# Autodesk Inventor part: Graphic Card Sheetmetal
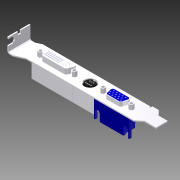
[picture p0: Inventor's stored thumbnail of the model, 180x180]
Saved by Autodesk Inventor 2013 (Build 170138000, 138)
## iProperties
Created: 2005-12
Material: Allgemein
Document SubType Name: Sheet Metal
Mass: 18.5516 g
Surface Area: 105.188 cm^2
Volume: 18.5516 cm^3
Density: 1 g/cm^3
Sheet Metal Rule: 1.0 mm
Author: Autodesk, Inc.
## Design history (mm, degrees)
node "Face1"
node "Flange1"
node "Face2"
sketch "Sketch5"
  geometry: L1 (108, 0)-(0, 0) reference; L2 (108, 18.5)-(108, 0) reference; L3 (108, 18.5)-(90.571, 18.5) reference; L4 (108, 9.25)-(96.897, 9.25); L5 (96, 18.5)-(100, 14.25); L6 (100, 14.25)-(108, 14.25); L7 (93, 0)-(98, 4.25); L8 (98, 4.25)-(108, 4.25)
  constraints: 10 end point, 4 point on line, 2 parallel, 1 midpoint, 1 perpendicular, 1 other
  dimensions: "d32" = 10 distance between parallel lines of L8 L6; "d33" = 12 distance from line of L5.start L2; "d34" = 15 distance from line of L2 L7.start; "d35" = 8 distance of L5.end L6.end; "d36" = 10 distance of L7.end L8.end
cut "Cut2" sketch "Sketch5" dims "d37" = 1 (= Thickness), "d38" = 0
node "Flange2"
sketch "Sketch7" dims "d47" = 5
  geometry: L1 (0, 0)-(0, 19) reference; L2 (10.5, 0)-(0, 0) reference; L3 (1.5, 0)-(6.5, 0); L4 (6.5, 0)-(6.5, 3); L5 (6.5, 3)-(1.5, 3); L6 (1.5, 3)-(1.5, 0); L7 (0, 9.5)-(6.587, 9.5); L8 (0, 10.75)-(2.5, 10.75); L9 (2.5, 10.75)-(2.5, 8.25); L10 (2.5, 8.25)-(0, 8.25); L11 (0, 8.25)-(0, 10.75); 1 further point
  constraints: 18 end point, 4 parallel, 4 perpendicular, 2 horizontal, 2 midpoint, 2 point on line, 1 horizontal alignment, 3 other
  dimensions: "d46" = 2.5 distance of L8.start L8.end; "d166" = 3 distance between parallel lines of L2 L5; "d167" = 4 distance from line of point (4, 3) L1
cut "Cut3" sketch "Sketch7" dims "d48" = 1 (= Thickness), "d49" = 0
sketch "Sketch8"
  geometry: L1 (-18.429, -2.75)-(-18.429, -12.75) reference; L2 (-3.429, -17)-(89.571, -17) reference; L3 (3.571, -2)-(34.071, -2); L4 (34.071, -2)-(34.071, -14); L5 (34.071, -14)-(3.571, -14); L6 (3.571, -14)-(3.571, -2)
  constraints: 8 end point, 2 parallel, 1 horizontal, 1 perpendicular
  dimensions: "d50" = 22 distance between parallel lines of L1 L6; "d51" = 30.5 distance of L3.start L3.end; "d52" = 12 distance of L3.end L4.end; "d53" = 3 distance between parallel lines of L2 L5
extrude "Extrusion1" join sketch "Sketch8" distance "d54" = 18; taper "d55" = 0 deg
sketch "Sketch9"
  geometry: L1 (30.5, 0)-(0, 0) reference; L2 (30.5, -18)-(30.5, 0) reference; L3 (30.5, 0)-(24.5, 0); L4 (24.5, 0)-(24.5, -10); L5 (24.5, -10)-(30.5, -10); L6 (30.5, -10)-(30.5, 0); L7 (0, 0)-(6, 0); L8 (6, 0)-(6, -10); L9 (6, -10)-(0, -10); L10 (0, -10)-(0, 0)
  constraints: 16 end point, 4 parallel, 2 collinear, 2 horizontal, 2 perpendicular
  dimensions: "d56" = 6 distance between parallel lines of L2 L4; "d57" = 10 distance between parallel lines of L5 L1
extrude "Extrusion2" cut sketch "Sketch9" distance "d58" = 10; taper "d59" = 0 deg
sketch "Sketch10"
  geometry: L1 (0, 0)-(0, 8) reference; L2 (30.5, 0)-(30.5, 8) reference; L3 (24.5, 18)-(6, 18) reference; L4 (0, 4)-(30.5, 4); L5 (30.5, 4)-(30.5, 18); L6 (30.5, 18)-(0, 18); L7 (0, 18)-(0, 4)
  constraints: 8 end point, 2 collinear, 2 parallel, 1 horizontal, 1 midpoint, 1 perpendicular
extrude "Extrusion3" cut sketch "Sketch10" distance "d60" = 1; taper "d61" = 0 deg
sketch "Sketch11"
  geometry: L1 (24.5, -10)-(30.5, -10) reference; L2 (24.5, 0)-(30.5, 0) reference; L3 (0, -10)-(6, -10) reference; L4 (6, -10)-(6, 0) reference; L5 (0, 0)-(6, 0) reference; L6 (0, -10)-(0, 0) reference; L7 (27.5, 0)-(27.5, -10); L8 (3, 0)-(3, -10); L9 (25.5, 0)-(29.5, 0); L10 (29.5, 0)-(29.5, -6); L11 (29.5, -6)-(25.5, -6); L12 (25.5, -6)-(25.5, 0); L13 (1, 0)-(5, 0); L14 (5, 0)-(5, -6); L15 (5, -6)-(1, -6); L16 (1, -6)-(1, 0); 2 further points
  constraints: 20 end point, 6 midpoint, 5 parallel, 2 horizontal, 2 horizontal alignment, 2 perpendicular, 2 point on line, 6 other
  dimensions: "d63" = 4 distance between parallel lines of L10 L12; "d64" = 6 distance between parallel lines of L15 L13
extrude "Extrusion4" cut sketch "Sketch11" stored distance "d65" = 0.5; taper "d66" = 0 deg
sketch "Sketch12"
  geometry: L1 (97.571, -17)-(4.571, -17) reference; L2 (90.571, -2)-(60.071, -2) reference; L3 (75.321, -2)-(75.321, -17); L4 (69.321, -5)-(81.321, -5); L5 (83.262, -7.485)-(82.262, -11.485); L6 (80.321, -13)-(70.321, -13); L7 (68.381, -11.485)-(67.381, -7.485); A1 r 2 centre (69.321, -7) between (69.321, -5) and (67.381, -7.485); A2 r 2 centre (81.321, -7) between (83.262, -7.485) and (81.321, -5); A3 r 2 centre (70.321, -11) between (68.381, -11.485) and (70.321, -13); A4 r 2 centre (80.321, -11) between (80.321, -13) and (82.262, -11.485)
  constraints: 10 end point, 8 point on circle, 8 tangent, 4 centre point, 2 equal radius, 2 perpendicular, 1 midpoint, 1 parallel, 1 point on line, 1 other
  dimensions: "d73" = 8 distance between parallel lines of L6 L4; "d74" = 4 distance between parallel lines of L1 L6; "d75" = 2 radius of A1; "d76" = 16 dimension on A2 A1; "d77" = 2 radius of A3; "d78" = 10 distance of L6.start L6.end
extrude "Extrusion5" join sketch "Sketch12" distance "d79" = 3.5; taper "d80" = 0 deg
sketch "Sketch13"
  geometry: L1 (69.321, -5)-(81.321, -5) reference; L2 (80.321, -13)-(70.321, -13) reference; L3 (75.321, -5)-(75.321, -13); L4 (75.321, -9)-(79.071, -9); L5 (70.321, -7)-(80.321, -7); L6 (77.821, -7)-(79.071, -9); L7 (80.321, -7)-(79.071, -9); L8 (70.321, -11)-(80.321, -11); C1 r 0.5 at (75.321, -7); C2 r 0.5 at (77.821, -7); C3 r 0.5 at (80.321, -7); C4 r 0.5 at (72.821, -7); C5 r 0.5 at (70.321, -7); C6 r 0.5 at (79.071, -9); C7 r 0.5 at (76.571, -9); C8 r 0.5 at (74.071, -9); C9 r 0.5 at (71.571, -9); C10 r 0.5 at (69.071, -9); C11 r 0.5 at (80.321, -11); C12 r 0.5 at (77.821, -11); C13 r 0.5 at (75.321, -11); C14 r 0.5 at (70.321, -11); C15 r 0.5 at (72.821, -11); A1 r 2 centre (69.321, -7) between (69.321, -5) and (67.381, -7.485) reference; 1 further point
  constraints: 15 centre point, 12 end point, 9 equal radius, 9 symmetric about line, 7 point on line, 5 coincident, 5 midpoint, 4 horizontal alignment, 1 equal length, 1 parallel, 1 perpendicular, 5 other
  dimensions: "d81" = 2 distance between parallel lines of L5 L1; "d82" = 2.5 distance of L6.start C1.centre (= d83); "d83" = 2.5 distance of L5.end L6.start; "d84" = 2.5 distance of C1.centre C4.centre (= d82); "d85" = 1 diameter of C3; "d86" = 2.5 distance of L4.end C7.centre (= d83); "d87" = 2.5 distance of C7.centre C8.centre (= d86); "d88" = 2.5 distance of C8.centre C9.centre (= d87); "d89" = 2.5 distance of C9.centre C10.centre (= d88)
extrude "Extrusion6" cut sketch "Sketch13" distance "d90" = 8; taper "d91" = 0 deg
split "Split1"
sketch "Sketch15"
  geometry: L1 (97.571, -17)-(4.571, -17) reference; L2 (112.571, -2.75)-(112.571, -12.75) reference; C1 r 5 at (50.571, -8)
  constraints: 1 centre point
  dimensions: "d93" = 9 distance from line of L1 C1.centre; "d94" = 62 distance from line of L2 C1.centre; "d95" = 10 diameter of C1
extrude "Extrusion7" cut sketch "Sketch15" stored distance "d96" = 8; taper "d97" = 0 deg
sketch "Sketch16"
  geometry: L1 (-3.429, -17)-(89.571, -17) reference; L2 (34.211, -2)-(52.932, -2); L3 (52.932, -2)-(52.932, -14); L4 (52.932, -14)-(34.211, -14); L5 (34.211, -14)-(34.211, -2); L6 (43.571, -8)-(43.571, -2); C1 r 5 at (43.571, -8) reference
  constraints: 10 end point, 2 parallel, 1 horizontal, 1 midpoint, 1 perpendicular, 1 vertical
  dimensions: "d98" = 3 distance between parallel lines of L1 L4; "d99" = 18.72091 distance of L2.start L2.end; "d100" = 12 distance of L2.end L3.end
extrude "Extrusion8" join sketch "Sketch16" distance "d101" = 15; taper "d102" = 0 deg
sketch "Sketch18"
  geometry: L1 (0, 0)-(0, 4); L2 (-1.25, 4.841)-(-1.25, 3); L3 (-1.25, 3)-(1.25, 3); L4 (1.25, 3)-(1.25, 4.841); L5 (-3.122, -2.5)-(-1.622, -2.5); L6 (-1.622, -2.5)-(-1.622, -3.656); L7 (1.622, -3.656)-(1.622, -2.5); L8 (1.622, -2.5)-(3.122, -2.5); L9 (-3.122, -2.5)-(-3.479, -2.5); C1 r 0.5 at (0, 1.5); C2 r 0.5 at (1.5, 1.5); C3 r 0.5 at (-1.5, 1.5); C4 r 0.5 at (-0.75, -1.5); C5 r 0.5 at (0.75, -1.5); C6 r 0.5 at (-2.25, -1.5); C7 r 0.5 at (2.25, -1.5); A1 r 5 centre (0, 0) between (-1.25, 4.841) and (1.25, 4.841) reference; A2 r 4 centre (0, 0) between (0, 4) and (-3.122, -2.5); A3 r 4 centre (0, 0) between (3.122, -2.5) and (1.25, 3.8); 1 further point
  constraints: 18 end point, 10 point on circle, 9 centre point, 6 equal radius, 5 horizontal alignment, 4 perpendicular, 3 parallel, 3 symmetric about line, 2 coincident, 2 collinear, 1 point on line, 1 vertical, 5 other
  dimensions: "d110" = 8 diameter of A2; "d111" = 2.5 distance from line of L5 A1.centre; "d112" = 1.5 distance of L5.start L5.end; "d113" = 3 distance from line of A1.centre L3; "d114" = 2.5 distance of L2.end L3.end; "d115" = 1 diameter of C2; "d116" = 1.5 distance of C2.centre C1.centre; "d117" = 1.5 distance of C4.centre C5.centre (= d116); "d118" = 1.5 distance of C5.centre C7.centre (= d117); "d119" = 1.5 distance of A1.centre C1.centre; "d120" = 1.5 vertical distance of C5.centre A1.centre (= d119)
extrude "Extrusion10" cut sketch "Sketch18" distance "d121" = 1; taper "d122" = 0 deg
sketch "Sketch19"
  geometry: L1 (-1.25, 4.841)-(-1.25, 3) reference; L2 (1.25, 3)-(1.25, 4.841) reference; L3 (-1.25, 3.8)-(-1.25, 3); L4 (-1.25, 3)-(1.25, 3); L5 (1.25, 3)-(1.25, 3.8); L6 (-3.122, -2.5)-(-1.622, -2.5) reference; L7 (1.622, -2.5)-(3.122, -2.5) reference; L8 (-1.622, -2.5)-(-3.122, -2.5); L9 (-1.622, -2.5)-(-1.632, -3.652); L10 (1.622, -2.5)-(1.63, -3.653); L11 (1.622, -2.5)-(3.122, -2.5); A1 r 5 centre (0, 0) between (-1.25, 4.841) and (1.25, 4.841) reference; A2 r 4 centre (0, 0) between (-3.122, -2.5) and (3.122, -2.5) reference; A3 r 4 centre (0, 0) between (-1.25, 3.8) and (1.25, 3.8)
  constraints: 14 end point, 6 point on circle, 3 collinear, 2 point on line, 1 centre point, 1 coincident, 1 concentric, 1 perpendicular
extrude "Extrusion11" cut sketch "Sketch19" distance "d123" = 1; taper "d124" = 0 deg
sketch "Sketch20"
  geometry: L1 (-44.821, -5)-(-44.821, -4.2) reference; L2 (-46.694, -10.5)-(-45.194, -10.5) reference; L3 (-45.194, -10.5)-(-45.203, -11.652) reference; L4 (-41.941, -11.653)-(-41.949, -10.5) reference; L5 (-41.949, -10.5)-(-40.449, -10.5) reference; L6 (-42.321, -4.2)-(-42.321, -5) reference; L7 (-42.321, -5)-(-44.821, -5) reference; C1 r 0.5 at (-45.821, -9.5) reference; C2 r 0.5 at (-44.321, -9.5) reference; C3 r 0.5 at (-42.071, -6.5) reference; C4 r 0.5 at (-43.571, -6.5) reference; C5 r 0.5 at (-45.071, -6.5) reference; C6 r 0.5 at (-42.821, -9.5) reference; C7 r 0.5 at (-41.321, -9.5) reference; A1 r 4 centre (-43.571, -8) between (-44.821, -4.2) and (-46.694, -10.5) reference; A2 r 4 centre (-43.571, -8) between (-45.203, -11.652) and (-41.941, -11.653) reference; A3 r 4 centre (-43.571, -8) between (-40.449, -10.5) and (-42.321, -4.2) reference
extrude "Extrusion12" join sketch "Sketch20" distance "d125" = 1; taper "d126" = 0 deg
sketch "Sketch21"
  geometry: L1 (13.071, -4.5)-(34.071, -4.5); L2 (35.944, -7.202)-(34.444, -11.202); L3 (32.571, -12.5)-(14.571, -12.5); L4 (12.699, -11.202)-(11.199, -7.202); L5 (80.321, -13)-(70.321, -13) reference; L6 (80.321, -12.5)-(70.321, -12.5) reference; L7 (23.571, -4.5)-(23.571, -1.134); L8 (112.571, -2.75)-(112.571, -12.75) reference; A1 r 2 centre (13.071, -6.5) between (13.071, -4.5) and (11.199, -7.202); A2 r 2 centre (34.071, -6.5) between (35.944, -7.202) and (34.071, -4.5); A3 r 2 centre (14.571, -10.5) between (12.699, -11.202) and (14.571, -12.5); A4 r 2 centre (32.571, -10.5) between (32.571, -12.5) and (34.444, -11.202)
  constraints: 10 end point, 8 point on circle, 8 tangent, 4 centre point, 3 equal radius, 1 collinear, 1 equal length, 1 horizontal, 1 midpoint, 1 parallel, 1 perpendicular
  dimensions: "d130" = 2 radius of A1; "d131" = 8 distance between parallel lines of L3 L1; "d132" = 25 dimension on A2 A1; "d133" = 18 distance of L3.start L3.end; "d134" = 89 distance between parallel lines of L8 L7
extrude "Extrusion13" join sketch "Sketch21" distance "d135" = 4.5; taper "d136" = 0 deg
sketch "Sketch22"
  geometry: L1 (13.071, -4.5)-(34.071, -4.5) reference; L2 (32.571, -12.5)-(14.571, -12.5) reference; L3 (13.571, -6)-(15.171, -6); L4 (15.171, -6)-(15.171, -7.6); L5 (15.171, -7.6)-(13.571, -7.6); L6 (13.571, -7.6)-(13.571, -6); L7 (13.571, -7.7)-(15.171, -7.7); L8 (15.171, -7.7)-(15.171, -9.3); L9 (15.171, -9.3)-(13.571, -9.3); L10 (13.571, -9.3)-(13.571, -7.7); L11 (13.571, -9.4)-(15.171, -9.4); L12 (15.171, -9.4)-(15.171, -11); L13 (15.171, -11)-(13.571, -11); L14 (13.571, -11)-(13.571, -9.4); A1 r 2 centre (13.071, -6.5) between (13.071, -4.5) and (11.199, -7.202) reference
  constraints: 24 end point, 6 parallel, 5 equal length, 3 horizontal, 3 perpendicular, 2 collinear
  dimensions: "d137" = 1.5 distance between parallel lines of L1 L3; "d138" = 1.5 distance between parallel lines of L2 L13 (= d137); "d139" = 0.5 distance from line of A1.centre L6; "d140" = 0.1 distance between parallel lines of L7 L5; "d141" = 0.1 distance between parallel lines of L11 L9 (= d140); "d142" = 1.6 distance of L3.start L3.end (derived)
extrude "Extrusion14" cut sketch "Sketch22" distance "d143" = 2; taper "d144" = 0 deg
pattern_linear "Rectangular Pattern1" dims "d147" = 1.7
sketch "Sketch24"
  geometry: L1 (53.071, -1)-(88.071, -1); L2 (88.071, -1)-(88.071, -14); L3 (88.071, -14)-(53.071, -14); L4 (53.071, -14)-(53.071, -1); L5 (52.932, -14)-(34.211, -14) reference; L6 (81.071, -4.5)-(60.071, -4.5) reference; L7 (70.571, -4.5)-(70.571, 4.593)
  constraints: 10 end point, 2 parallel, 2 perpendicular, 1 collinear, 1 horizontal, 1 midpoint, 1 other
  dimensions: "d156" = 35 distance of L1.start L1.end; "d157" = 13 distance of L1.end L2.end
extrude "Extrusion16" join sketch "Sketch24" distance "d158" = 15; taper "d159" = 0 deg
sketch "Sketch25"
  geometry: L1 (35.944, -7.202)-(34.444, -11.202) reference; L2 (12.699, -11.202)-(11.199, -7.202) reference; L3 (94.143, 0)-(0, 0) reference; L4 (60.071, -12)-(66.071, -12) reference; L5 (84.571, -12)-(90.571, -12) reference; L6 (63.071, -12)-(63.071, -3.646); L7 (87.571, -12)-(87.571, -3.646); L8 (35.194, -9.202)-(38.194, -9.202); L9 (87.571, -11.202)-(85.839, -10.202); L10 (85.839, -10.202)-(85.839, -8.202); L11 (85.839, -8.202)-(87.571, -7.202); L12 (87.571, -7.202)-(89.303, -8.202); L13 (89.303, -8.202)-(89.303, -10.202); L14 (89.303, -10.202)-(87.571, -11.202); L15 (63.071, -11.202)-(61.339, -10.202); L16 (61.339, -10.202)-(61.339, -8.202); L17 (61.339, -8.202)-(63.071, -7.202); L18 (63.071, -7.202)-(64.803, -8.202); L19 (64.803, -8.202)-(64.803, -10.202); L20 (64.803, -10.202)-(63.071, -11.202); L21 (38.103, -11.2)-(36.418, -10.122); L22 (36.418, -10.122)-(36.509, -8.124); L23 (36.509, -8.124)-(38.285, -7.204); L24 (38.285, -7.204)-(39.97, -8.282); L25 (39.97, -8.282)-(39.879, -10.28); L26 (39.879, -10.28)-(38.103, -11.2); L27 (9.758, -11.031)-(7.769, -10.818); L28 (7.769, -10.818)-(6.96, -8.989); L29 (6.96, -8.989)-(8.14, -7.373); L30 (8.14, -7.373)-(10.128, -7.587); L31 (10.128, -7.587)-(10.937, -9.416); L32 (10.937, -9.416)-(9.758, -11.031); L33 (11.949, -9.202)-(8.949, -9.202); C1 r 1.25 at (8.949, -9.202); C2 r 1.25 at (38.194, -9.202); C3 r 1.25 at (63.071, -9.202); C4 r 1.25 at (87.571, -9.202); 3 further points
  constraints: 56 end point, 6 point on line, 4 centre point, 4 coincident, 4 equal length, 4 midpoint, 3 equal radius, 3 horizontal alignment, 3 perpendicular, 1 parallel, 44 other
  dimensions: "d160" = 2 distance of L12.end L13.end; "d161" = 3 distance of L33.start L33.end; "d162" = 3 distance of point (38.194, -9.202) L8.start; "d163" = 2.5 diameter of C4
extrude "Extrusion17" join sketch "Sketch25" distance "d164" = 4; taper "d165" = 0 deg
fillet "Fillet1" dims "d62" = 2
sketch "Sketch23"
  geometry: L1 (27.071, -7.7)-(27.071, -9.3) reference; L2 (28.071, -8.4)-(33.071, -8.4); L3 (33.071, -8.4)-(33.071, -8.6); L4 (33.071, -8.6)-(28.071, -8.6); L5 (28.071, -8.6)-(28.071, -8.4); L6 (30.471, -6)-(30.671, -6); L7 (30.671, -6)-(30.671, -11); L8 (30.671, -11)-(30.471, -11); L9 (30.471, -11)-(30.471, -6); L10 (27.071, -8.5)-(25.088, -8.5); L11 (30.571, -8.4)-(30.571, -7.951); L12 (28.571, -6.5)-(29.571, -6.5); L13 (29.571, -6.5)-(29.571, -7.5); L14 (29.571, -7.5)-(28.571, -7.5); L15 (28.571, -7.5)-(28.571, -6.5); L16 (31.571, -6.5)-(32.571, -6.5); L17 (32.571, -6.5)-(32.571, -7.5); L18 (32.571, -7.5)-(31.571, -7.5); L19 (31.571, -7.5)-(31.571, -6.5); L20 (28.571, -9.5)-(29.571, -9.5); L21 (29.571, -9.5)-(29.571, -10.5); L22 (29.571, -10.5)-(28.571, -10.5); L23 (28.571, -10.5)-(28.571, -9.5); L24 (31.571, -9.5)-(32.571, -9.5); L25 (32.571, -9.5)-(32.571, -10.5); L26 (32.571, -10.5)-(31.571, -10.5); L27 (31.571, -10.5)-(31.571, -9.5)
  constraints: 52 end point, 12 parallel, 9 equal length, 8 perpendicular, 6 horizontal, 4 collinear, 2 midpoint, 5 other
  dimensions: "d148" = 5 distance of L6.end L7.end; "d149" = 3.5 distance between parallel lines of L1 L11; "d150" = 0.2 distance of L2.end L3.end; "d151" = 1 distance of L12.start L12.end; "d152" = 1 distance between parallel lines of L10 L14; "d153" = 1 distance between parallel lines of L13 L11
extrude "Extrusion15" cut sketch "Sketch23" distance "d154" = 2; taper "d155" = 0 deg
body "Solid1"
sketch "Sketch1"
  geometry: L1 (0, 21.7)-(0, -7.7) reference; L2 (-145.2, 0)-(24.2, 0) reference; L3 (0, 0)-(-108, 0); L4 (-108, 0)-(-116, -3.5); L5 (-116, -3.5)-(-121, -3.5); L6 (-121, -3.5)-(-121, 15.5); L7 (-121, 15.5)-(-116, 15.5); L8 (-116, 15.5)-(-111.429, 17.5); L9 (-111.429, 17.5)-(0, 17.5); L10 (0, 0)-(0, 17.5)
  constraints: 16 end point, 3 parallel, 3 point on line, 2 perpendicular, 1 collinear, 1 horizontal
  dimensions: "d2" = 121 distance between parallel lines of L1 L6; "d3" = 17.5 distance between parallel lines of L3 L9; "d4" = 13 distance from line of L3.end L6; "d5" = 5 distance of L4.end L5.end; "d6" = 5 distance of L6.end L7.end (= d5); "d7" = 19 distance of L5.end L6.end; "d9" = 2 distance between parallel lines of L7 L9
face "Plate1" dims "Thickness" = 1
sketch "Sketch3"
  geometry: L1 through (46.5, 0) direction (1, 7.14e-34); L2 (93, 0)-(93, -2); L3 (93, -2)-(0, -2); L4 through (0, -1) direction (-0, 1)
  constraints: 6 end point, 1 horizontal, 1 perpendicular, 1 vertical
face "Plate2" dims "d17" = 0, "d18" = 93, "d19" = 1 (= BendReliefWidth), "d21" = 2 (= MinimumRemnant), "d23" = 2, "d24" = 90 deg, "d25" = 0.5, "Thickness" = 1
bend "Bend1" dims "d19" = 1 (= BendReliefWidth), "d20" = 0.5 (= BendReliefDepth), "d21" = 2 (= MinimumRemnant), "d22" = 1 (= BendRadius), "d23" = 2, "d24" = 90 deg, "d25" = 0.5, "SeamGap" = 0.01, "Thickness" = 1
sketch "Sketch4"
  geometry: L1 (108, 0)-(0, 0) reference; L2 (108, 17.5)-(108, 0) reference; L3 (90.571, 17.5)-(108, 17.5); L4 (108, 17.5)-(108, 18.5); L5 (108, 18.5)-(90.571, 18.5); L6 (90.571, 18.5)-(90.571, 17.5)
  constraints: 8 end point, 2 parallel, 1 collinear, 1 horizontal, 1 perpendicular
  dimensions: "d26" = 18.5 distance between parallel lines of L1 L5
face "Plate3" dims "d27" = 1 (= BendRadius), "d30" = 2 (= MinimumRemnant), "SeamGap" = 0.01, "Thickness" = 1
bend "Bend2" dims "d27" = 1 (= BendRadius), "d28" = 1 (= BendReliefWidth), "d29" = 0.5 (= BendReliefDepth), "d30" = 2 (= MinimumRemnant), "d31" = 1 (= BendRadius), "SeamGap" = 0.01, "Thickness" = 1
sketch "Sketch6"
  geometry: L1 through (-9.5, 0) direction (-1, 0); L2 (-19, 0)-(-19, 12.5); L3 (-19, 12.5)-(0, 12.5); L4 through (0, 6.25) direction (0, -1)
  constraints: 6 end point, 1 horizontal, 1 perpendicular, 1 vertical
face "Plate4" dims "d41" = 2 (= MinimumRemnant), "d43" = 12.5, "d44" = 90 deg, "d45" = 1 (= BendRadius), "SeamGap" = 0.01, "Thickness" = 1
bend "Bend3" dims "d39" = 1 (= BendReliefWidth), "d40" = 0.5 (= BendReliefDepth), "d41" = 2 (= MinimumRemnant), "d42" = 1 (= BendRadius), "d43" = 12.5, "d44" = 90 deg, "d45" = 1 (= BendRadius), "SeamGap" = 0.01, "Thickness" = 1
node "Projected Loop1"
sketch "Sketch14"
  geometry: L1 (69.321, -5)-(81.321, -5) reference; L2 (68.381, -11.485)-(67.381, -7.485) reference; L3 (80.321, -13)-(70.321, -13) reference; L4 (83.262, -7.485)-(82.262, -11.485) reference; L5 (81.321, -5.5)-(69.321, -5.5); L6 (67.866, -7.364)-(68.866, -11.364); L7 (70.321, -12.5)-(80.321, -12.5); L8 (81.777, -11.364)-(82.777, -7.364); A1 r 2 centre (69.321, -7) between (69.321, -5) and (67.381, -7.485) reference; A2 r 2 centre (70.321, -11) between (68.381, -11.485) and (70.321, -13) reference; A3 r 2 centre (80.321, -11) between (80.321, -13) and (82.262, -11.485) reference; A4 r 2 centre (81.321, -7) between (83.262, -7.485) and (81.321, -5) reference; A5 r 1.5 centre (69.321, -7) between (69.321, -5.5) and (67.866, -7.364); A6 r 1.5 centre (70.321, -11) between (68.866, -11.364) and (70.321, -12.5); A7 r 1.5 centre (80.321, -11) between (80.321, -12.5) and (81.777, -11.364); A8 r 1.5 centre (81.321, -7) between (82.777, -7.364) and (81.321, -5.5)
  constraints: 8 end point, 8 point on circle, 4 centre point, 7 other
  dimensions: "d92" = 0.5 distance between parallel lines of L1 L5
other parameters: "BendRadius" = 1 (= Thickness), "BendReliefWidth" = 1 (= Thickness), "BendReliefDepth" = 0.5 (= 0.5 x Thickness), "CornerReliefSize" = 4 (= 4 x Thickness), "MinimumRemnant" = 2 (= 2 x Thickness), "TransitionRadius" = 1 (= BendRadius), "d10" = 1 (= BendRadius), "JacobiRadiusSize" = 1 (= Thickness), "GapSize" = 1 (= Thickness)
